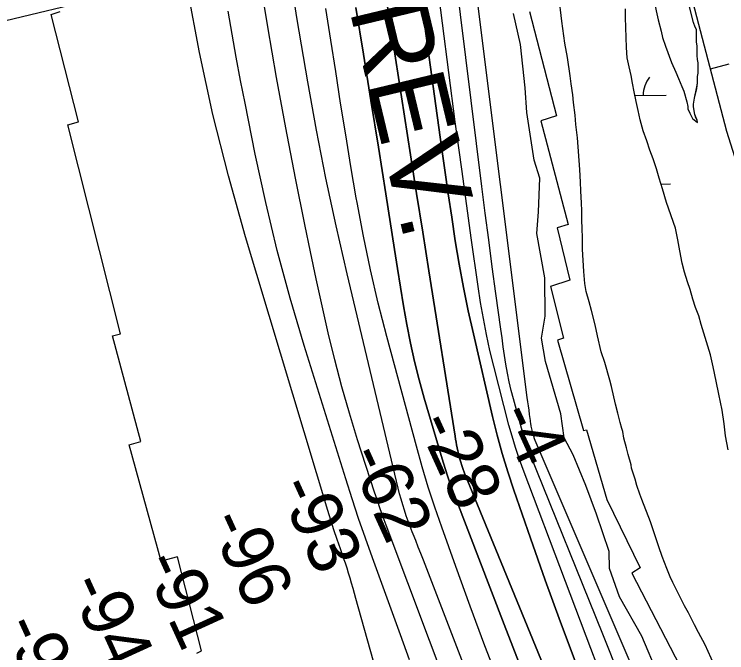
# Model space of a CAD drawing. Extents: x 3567028 to 3605064, y 510945 to 536587.
# Drawn here: x 3578355 to 3579281, y 531241 to 532071 of the extents above; entities that cross this region are included whole.
import ezdxf

# ---------------------------------------------------------------- set-up
doc = ezdxf.new("R2010")
doc.units = 0
for name, color, linetype in [('V-BORW-LINE', 7, 'Continuous'), ('V-RIVR-EDGE', 7, 'Continuous'), ('V-RIVR-RANG', 7, 'Continuous'), ('V-RRAP-RVMT', 7, 'Continuous'), ('V-RRAP-RVMT-IDEN', 7, 'Continuous'), ('V-SITE-VEGE', 7, 'Continuous'), ('V-TOPO-DPTH', 7, 'Continuous'), ('V-TOPO-MAJR', 7, 'Continuous'), ('V-TOPO-MINR', 7, 'Continuous'), ('V-WETL-SWMP', 7, 'Continuous')]:
    doc.layers.add(name, color=color, linetype=linetype)

msp = doc.modelspace()

# ---------------------------------------------------------------- linework, layer by layer
at = {"layer": 'V-BORW-LINE'}
msp.add_line((3579260.25, 531999.86), (3579284.44, 532006.19), dxfattribs=at)
msp.add_lwpolyline([(3579544.69, 531115.58), (3579495.04, 531277.88), (3579451.04, 531433.5), (3579380.8, 531627.25), (3579329.97, 531764.6), (3579281.59, 531918.4), (3579230.4, 532113.84)], dxfattribs=at)
at = {"layer": 'V-RIVR-EDGE'}
msp.add_lwpolyline([(3579192.44, 531212.2), (3579171.12, 531262.49), (3579141.83, 531313.42), (3579129.05, 531350.22), (3579128.5, 531372.28), (3579112.07, 531420.72), (3579098.07, 531458.13), (3579081.63, 531498), (3579070.04, 531520.09), (3579065.83, 531551.35), (3579045.78, 531619.41), (3579040.34, 531649.45), (3579045.31, 531678.23), (3579044.82, 531727.87), (3579034.55, 531785.49), (3579036.45, 531813.67), (3579038.4, 531857.78), (3579031.11, 531881.08), (3579021.46, 531942.99), (3579019.08, 531974.86), (3579013.1, 532031.24), (3579004, 532071.71)], dxfattribs=at)
at = {"layer": 'V-RIVR-RANG'}
msp.add_line((3579599.9, 532363.51), (3578219.06, 532032.29), dxfattribs=at)
at = {"layer": 'V-RRAP-RVMT'}
for p, q in [((3578402.67, 532070.27), (3578414.66, 532074.07)), ((3578438.32, 531930.69), (3578402.67, 532070.27)), ((3579025.11, 532074.05), (3579060, 531938.56)), ((3579060, 531938.56), (3579039.5, 531932.16)), ((3578424.57, 531926.86), (3578438.32, 531930.69)), ((3579039.5, 531932.16), (3579075.14, 531797.42)), ((3578493.13, 531655.46), (3578424.57, 531926.86)), ((3579075.14, 531797.42), (3579061.04, 531793.05)), ((3579061.04, 531793.05), (3579077.29, 531725.1)), ((3579077.29, 531725.1), (3579052.32, 531716.62)), ((3579052.32, 531716.62), (3579069.06, 531649.64)), ((3578482.61, 531652.82), (3578493.13, 531655.46)), ((3578519.46, 531515.29), (3578482.61, 531652.82)), ((3579069.06, 531649.64), (3579061.46, 531647.06)), ((3579061.46, 531647.06), (3579095.27, 531529.8)), ((3579095.27, 531529.8), (3579098.94, 531530.7)), ((3579098.94, 531530.7), (3579125.69, 531440.08)), ((3578504.36, 531510.82), (3578519.46, 531515.29)), ((3578546.05, 531359.92), (3578504.36, 531510.82)), ((3579125.69, 531440.08), (3579168.82, 531351.3)), ((3578567.18, 531365.29), (3578546.05, 531359.92)), ((3578598.3, 531243.32), (3578567.18, 531365.29)), ((3579168.82, 531351.3), (3579158.16, 531344.38)), ((3579158.16, 531344.38), (3579220.44, 531223.82)), ((3578592.1, 531240.14), (3578598.3, 531243.32))]:
    msp.add_line(p, q, dxfattribs=at)
at = {"layer": 'V-SITE-VEGE'}
for points in [[(3579174.4, 532144.03), (3579176.51, 532136.23), (3579182.23, 532109.23), (3579185.24, 532096.33), (3579186.44, 532089.14), (3579192.46, 532063.34), (3579196.07, 532048.65), (3579197.88, 532040.55), (3579201.79, 532029.15)], [(3579131.52, 531587.05), (3579129.42, 531595.15), (3579122.8, 531618.24), (3579118.29, 531632.04), (3579113.17, 531652.73), (3579110.16, 531667.13), (3579105.35, 531685.72), (3579102.64, 531696.82), (3579098.73, 531710.32), (3579096.92, 531720.52), (3579095.41, 531736.11), (3579093.89, 531765.51), (3579093.88, 531777.51), (3579093.57, 531794.91), (3579092.96, 531800.31), (3579092.95, 531815.6), (3579092.65, 531825.2), (3579091.74, 531841.1), (3579091.43, 531852.2), (3579090.51, 531868.7), (3579087.48, 531909.8), (3579085.37, 531927.49), (3579084.16, 531939.49), (3579082.35, 531955.99), (3579081.14, 531965.89), (3579079.03, 531980.28), (3579077.82, 531990.78), (3579074.21, 532014.48), (3579070.9, 532033.07), (3579066.97, 532061.57), (3579063.05, 532095.16)], [(3579201.79, 532029.15), (3579209.6, 532007.86), (3579215.31, 531995.26), (3579218.62, 531987.17), (3579223.12, 531976.67), (3579225.53, 531970.67), (3579229.74, 531956.58), (3579230.95, 531950.58), (3579230.95, 531947.58), (3579233.35, 531941.88), (3579236.96, 531935.28), (3579243.56, 531929.89), (3579242.96, 531932.89), (3579241.46, 531935.89), (3579239.95, 531940.39), (3579239.05, 531944.88), (3579238.14, 531950.58), (3579238.14, 531953.58), (3579239.33, 531961.69), (3579242.33, 531973.98), (3579243.22, 531980.89), (3579243.22, 531983.89), (3579243.51, 531989.89), (3579244.11, 531994.09), (3579244.1, 532007.58), (3579243.5, 532011.78), (3579243.19, 532017.18), (3579242.88, 532029.48), (3579242.28, 532034.28), (3579241.97, 532041.78), (3579241.97, 532050.78), (3579240.17, 532053.78), (3579238.06, 532060.08), (3579232.95, 532080.17)], [(3579264.98, 531225.07), (3579253.56, 531251.16), (3579244.85, 531267.06), (3579239.45, 531277.25), (3579231.64, 531292.54), (3579226.53, 531301.84), (3579211.51, 531332.13), (3579207.9, 531339.62), (3579203.39, 531350.42), (3579200.39, 531357.92), (3579197.38, 531366.01), (3579193.17, 531378.31), (3579190.17, 531387.61), (3579182.35, 531411), (3579170.93, 531439.79), (3579168.52, 531446.99), (3579164.62, 531458.08), (3579162.21, 531466.48), (3579157.7, 531480.88), (3579157.1, 531485.07), (3579153.19, 531498.27), (3579151.08, 531507.27), (3579147.47, 531519.87), (3579146.26, 531528.56), (3579145.06, 531532.16), (3579142.96, 531539.96), (3579139.95, 531552.26), (3579136.94, 531563.95), (3579131.52, 531587.05)]]:
    msp.add_lwpolyline(points, dxfattribs=at)
at = {"layer": 'V-TOPO-DPTH'}
for points in [[(3579165.47, 531151.78), (3579120.36, 531264.91), (3579025.47, 531499.76), (3579022.78, 531506.76), (3579020.25, 531513.81), (3579017.95, 531520.94), (3579015.82, 531528.12), (3579003.97, 531570.69), (3579001.07, 531581.85), (3578998.44, 531593.06), (3578996.21, 531604.36), (3578994.24, 531615.72), (3578992.51, 531627.13), (3578990.81, 531638.54), (3578989.17, 531649.97), (3578987.58, 531661.39), (3578981.22, 531707.87), (3578976.53, 531742.55), (3578971.94, 531777.24), (3578967.47, 531811.95), (3578963.08, 531846.66), (3578900.86, 532346.53)], [(3578879.54, 532121.47), (3578910.52, 531898.44), (3578914.84, 531867.88), (3578919.26, 531837.33), (3578923.81, 531806.81), (3578928.47, 531776.3), (3578933.54, 531745.87), (3578939.06, 531715.52), (3578945.26, 531685.31), (3578951.91, 531655.18), (3578976.91, 531547.79), (3578982.92, 531523.66), (3578989.43, 531499.68), (3578996.69, 531475.92), (3579004.44, 531452.3), (3579026.07, 531389.74), (3579045.35, 531335.08), (3579065.09, 531280.58), (3579085.51, 531226.33)], [(3579085.51, 531226.33), (3579065.09, 531280.58), (3579045.35, 531335.08), (3579026.07, 531389.74), (3579004.44, 531452.3), (3578996.69, 531475.92), (3578989.43, 531499.68), (3578982.92, 531523.66), (3578976.91, 531547.79), (3578951.91, 531655.18), (3578945.26, 531685.31), (3578939.06, 531715.52), (3578933.54, 531745.87), (3578928.47, 531776.3), (3578923.81, 531806.81), (3578919.26, 531837.33), (3578914.84, 531867.88), (3578910.52, 531898.44), (3578879.54, 532121.47)], [(3578838.91, 532088.73), (3578846.63, 532038.46), (3578854.44, 531988.21), (3578862.31, 531937.97), (3578870.24, 531887.74), (3578878.18, 531837.5), (3578886.14, 531787.27), (3578894.11, 531737.05), (3578928.24, 531522.08), (3578928.85, 531518.34), (3578929.47, 531514.61), (3578930.12, 531510.87), (3578930.79, 531507.14), (3578931.54, 531503.43), (3578932.38, 531499.75), (3578933.37, 531496.09), (3578934.44, 531492.47), (3578938.26, 531480.44), (3578938.8, 531478.82), (3578939.97, 531475.6), (3578940.6, 531474), (3579080.39, 531133.25)], [(3579080.39, 531133.25), (3578940.6, 531474), (3578939.97, 531475.6), (3578938.8, 531478.82), (3578938.26, 531480.44), (3578934.44, 531492.47), (3578933.37, 531496.09), (3578932.38, 531499.75), (3578931.54, 531503.43), (3578930.79, 531507.14), (3578930.12, 531510.87), (3578929.47, 531514.61), (3578928.85, 531518.34), (3578928.24, 531522.08), (3578894.11, 531737.05), (3578886.14, 531787.27), (3578878.18, 531837.5), (3578870.24, 531887.74), (3578862.31, 531937.97), (3578854.44, 531988.21), (3578846.63, 532038.46), (3578838.91, 532088.73)], [(3578798.97, 532079.45), (3578808.91, 532018.92), (3578818.73, 531958.37), (3578828.38, 531897.79), (3578837.91, 531837.19), (3578849.2, 531764.7), (3578853.08, 531740.35), (3578857.06, 531716.02), (3578861.21, 531691.71), (3578865.46, 531667.42), (3578870.19, 531643.24), (3578875.45, 531619.18), (3578881.51, 531595.31), (3578888.09, 531571.57), (3578911.36, 531492.8), (3578915.2, 531480.38), (3578919.23, 531468.02), (3578923.56, 531455.77), (3578928.09, 531443.59), (3578992.11, 531277.63), (3579028.9, 531182.55)], [(3579028.9, 531182.55), (3578992.11, 531277.63), (3578928.09, 531443.59), (3578923.56, 531455.77), (3578919.23, 531468.02), (3578915.2, 531480.38), (3578911.36, 531492.8), (3578888.09, 531571.57), (3578881.51, 531595.31), (3578875.45, 531619.18), (3578870.19, 531643.24), (3578865.46, 531667.42), (3578861.21, 531691.71), (3578857.06, 531716.02), (3578853.08, 531740.35), (3578849.2, 531764.7), (3578837.91, 531837.19), (3578828.38, 531897.79), (3578818.73, 531958.37), (3578808.91, 532018.92), (3578798.97, 532079.45)]]:
    msp.add_lwpolyline(points, dxfattribs=at)
at = {"layer": 'V-TOPO-MAJR'}
msp.add_lwpolyline([(3578986.64, 531198.79), (3578967.04, 531249.93), (3578947.95, 531301.26), (3578929.19, 531352.72), (3578910.81, 531403.88), (3578901.81, 531429.95), (3578893.23, 531456.15), (3578885.3, 531482.56), (3578877.8, 531509.1), (3578839.3, 531651.93), (3578828.29, 531695.12), (3578818.07, 531738.49), (3578809.02, 531782.12), (3578800.77, 531825.92), (3578799.73, 531831.86), (3578792.72, 531872.85), (3578785.89, 531913.86), (3578779.32, 531954.91), (3578772.93, 531996), (3578766.58, 532037.09), (3578760.08, 532078.15)], dxfattribs=at)
at = {"layer": 'V-TOPO-MINR'}
for points in [[(3579226.28, 531064.84), (3579032.35, 531516.86), (3579031.52, 531518.95), (3579031.16, 531520.02), (3579030.82, 531521.09), (3579028.76, 531528.12), (3579028.27, 531529.93), (3579027.45, 531533.59), (3579027.13, 531535.44), (3579026.57, 531539.15), (3579026.31, 531541.01), (3579026.05, 531542.86), (3579025.03, 531550.34), (3579024.28, 531555.93), (3579023.54, 531561.53), (3579022.81, 531567.13), (3579022.1, 531572.73), (3578917.64, 532406.89)], [(3579165.47, 531151.78), (3579120.36, 531264.91), (3579025.47, 531499.76), (3579022.78, 531506.76), (3579020.25, 531513.81), (3579017.95, 531520.94), (3579015.82, 531528.12), (3579003.97, 531570.69), (3579001.07, 531581.85), (3578998.44, 531593.06), (3578996.21, 531604.36), (3578994.24, 531615.72), (3578992.51, 531627.13), (3578990.81, 531638.54), (3578989.17, 531649.97), (3578987.58, 531661.39), (3578981.22, 531707.87), (3578976.53, 531742.55), (3578971.94, 531777.24), (3578967.47, 531811.95), (3578963.08, 531846.66), (3578900.86, 532346.53)], [(3579137.85, 531159.64), (3579104.83, 531246.55), (3579071.83, 531333.48), (3579016.64, 531478.98), (3579011.5, 531493.24), (3579006.67, 531507.59), (3579002.31, 531522.1), (3578998.27, 531536.71), (3578978.49, 531613.06), (3578973.48, 531633.65), (3578968.89, 531654.33), (3578964.91, 531675.13), (3578961.35, 531696.02), (3578958.16, 531716.98), (3578955.04, 531737.95), (3578952.02, 531758.93), (3578949.07, 531779.93), (3578937.17, 531866.38), (3578928.45, 531930.63), (3578919.92, 531994.9), (3578911.64, 532059.2), (3578903.55, 532123.53)], [(3578923.07, 531181.66), (3578838.57, 531406.51), (3578834.62, 531417.23), (3578830.78, 531427.98), (3578827.08, 531438.78), (3578823.48, 531449.62), (3578801.44, 531517.58), (3578790.77, 531551.99), (3578780.73, 531586.57), (3578771.6, 531621.4), (3578763.08, 531656.4), (3578755.16, 531691.56), (3578747.44, 531726.76), (3578740, 531762.02), (3578732.74, 531797.32), (3578720.65, 531857.4), (3578707.94, 531922.85), (3578695.83, 531988.41), (3578684.62, 532054.13), (3578674.01, 532119.95)], [(3579085.51, 531226.33), (3579065.09, 531280.58), (3579045.35, 531335.08), (3579026.07, 531389.74), (3579004.44, 531452.3), (3578996.69, 531475.92), (3578989.43, 531499.68), (3578982.92, 531523.66), (3578976.91, 531547.79), (3578951.91, 531655.18), (3578945.26, 531685.31), (3578939.06, 531715.52), (3578933.54, 531745.87), (3578928.47, 531776.3), (3578923.81, 531806.81), (3578919.26, 531837.33), (3578914.84, 531867.88), (3578910.52, 531898.44), (3578879.54, 532121.47)], [(3578841.09, 531161.67), (3578799.2, 531311.24), (3578797.33, 531317.87), (3578795.46, 531324.49), (3578793.56, 531331.11), (3578791.66, 531337.72), (3578789.69, 531344.31), (3578787.64, 531350.88), (3578785.48, 531357.41), (3578783.23, 531363.91), (3578779.03, 531375.75), (3578774.71, 531388.19), (3578770.52, 531400.67), (3578766.51, 531413.2), (3578762.63, 531425.78), (3578655.59, 531781.28), (3578633.32, 531860.59), (3578613.05, 531940.37), (3578595.78, 532020.86), (3578580.51, 532101.81)], [(3579080.39, 531133.25), (3578940.6, 531474), (3578939.97, 531475.6), (3578938.8, 531478.82), (3578938.26, 531480.44), (3578934.44, 531492.47), (3578933.37, 531496.09), (3578932.38, 531499.75), (3578931.54, 531503.43), (3578930.79, 531507.14), (3578930.12, 531510.87), (3578929.47, 531514.61), (3578928.85, 531518.34), (3578928.24, 531522.08), (3578894.11, 531737.05), (3578886.14, 531787.27), (3578878.18, 531837.5), (3578870.24, 531887.74), (3578862.31, 531937.97), (3578854.44, 531988.21), (3578846.63, 532038.46), (3578838.91, 532088.73)], [(3578978.29, 531124.51), (3578886.88, 531361.27), (3578883.6, 531369.72), (3578880.3, 531378.16), (3578876.98, 531386.59), (3578873.64, 531395.01), (3578872.45, 531398), (3578869.75, 531404.95), (3578867.15, 531411.93), (3578864.67, 531418.96), (3578862.29, 531426.01), (3578860.06, 531433.12), (3578857.94, 531440.26), (3578856.01, 531447.45), (3578854.19, 531454.68), (3578787.63, 531733.42), (3578773.46, 531795.45), (3578760.11, 531857.66), (3578747.99, 531920.11), (3578736.68, 531982.73), (3578722.87, 532063.82), (3578719.16, 532086.03)], [(3579028.9, 531182.55), (3578992.11, 531277.63), (3578928.09, 531443.59), (3578923.56, 531455.77), (3578919.23, 531468.02), (3578915.2, 531480.38), (3578911.36, 531492.8), (3578888.09, 531571.57), (3578881.51, 531595.31), (3578875.45, 531619.18), (3578870.19, 531643.24), (3578865.46, 531667.42), (3578861.21, 531691.71), (3578857.06, 531716.02), (3578853.08, 531740.35), (3578849.2, 531764.7), (3578837.91, 531837.19), (3578828.38, 531897.79), (3578818.73, 531958.37), (3578808.91, 532018.92), (3578798.97, 532079.45)], [(3578868.66, 531231.47), (3578857.03, 531264.04), (3578820.56, 531364.09), (3578811.47, 531389.59), (3578802.62, 531415.17), (3578794.13, 531440.88), (3578785.89, 531466.67), (3578731.85, 531640.03), (3578713.71, 531701.59), (3578696.87, 531763.49), (3578681.97, 531825.88), (3578668.37, 531888.6), (3578655.08, 531954.87), (3578649.24, 531984.73), (3578643.59, 532014.64), (3578638.23, 532044.59), (3578633.06, 532074.58)]]:
    msp.add_lwpolyline(points, dxfattribs=at)
at = {"layer": 'V-WETL-SWMP'}
for p, q in [((3579186.44, 532089.13), (3579192.46, 532063.34)), ((3579149.85, 532066.32), (3579149.84, 532077.45)), ((3579238.05, 532060.08), (3579232.94, 532080.17)), ((3579151.06, 532027.53), (3579149.85, 532066.32)), ((3579192.46, 532063.34), (3579196.07, 532048.64)), ((3579240.16, 532053.78), (3579238.05, 532060.08)), ((3579241.96, 532050.78), (3579240.16, 532053.78)), ((3579241.97, 532041.78), (3579241.96, 532050.78)), ((3579196.07, 532048.64), (3579197.87, 532040.55)), ((3579197.87, 532040.55), (3579201.78, 532029.15)), ((3579242.27, 532034.28), (3579241.97, 532041.78)), ((3579242.88, 532029.48), (3579242.27, 532034.28)), ((3579151.85, 532013.9), (3579151.06, 532027.53)), ((3579201.78, 532029.15), (3579209.6, 532007.86)), ((3579243.19, 532017.18), (3579242.88, 532029.48)), ((3579154.48, 532002.37), (3579151.85, 532013.9)), ((3579243.49, 532011.78), (3579243.19, 532017.18)), ((3579209.6, 532007.86), (3579215.3, 531995.26)), ((3579244.09, 532007.58), (3579243.49, 532011.78)), ((3579244.1, 531994.08), (3579244.09, 532007.58)), ((3579156.98, 531990.84), (3579154.48, 532002.37)), ((3579215.3, 531995.26), (3579218.61, 531987.17)), ((3579243.51, 531989.88), (3579244.1, 531994.08)), ((3579158.95, 531980.88), (3579156.98, 531990.84)), ((3579218.61, 531987.17), (3579223.12, 531976.67)), ((3579243.21, 531983.88), (3579243.51, 531989.88)), ((3579161.19, 531969.88), (3579158.95, 531980.88)), ((3579223.12, 531976.67), (3579225.52, 531970.67)), ((3579242.32, 531973.98), (3579243.21, 531980.88)), ((3579243.21, 531980.88), (3579243.21, 531983.88)), ((3579163.69, 531957.04), (3579161.19, 531969.88)), ((3579225.52, 531970.67), (3579229.73, 531956.58)), ((3579239.33, 531961.68), (3579242.32, 531973.98)), ((3579162.13, 531965.06), (3579202.82, 531965.41)), ((3579166.19, 531945.38), (3579163.69, 531957.04)), ((3579238.13, 531953.58), (3579239.33, 531961.68)), ((3579229.73, 531956.58), (3579230.94, 531950.58)), ((3579230.94, 531950.58), (3579230.94, 531947.58)), ((3579230.94, 531947.58), (3579233.34, 531941.88)), ((3579238.14, 531950.58), (3579238.13, 531953.58)), ((3579239.04, 531944.88), (3579238.14, 531950.58)), ((3579168.95, 531933.59), (3579166.19, 531945.38)), ((3579233.34, 531941.88), (3579236.95, 531935.28)), ((3579239.94, 531940.39), (3579239.04, 531944.88)), ((3579241.45, 531935.89), (3579239.94, 531940.39)), ((3579172.63, 531919.18), (3579168.95, 531933.59)), ((3579236.95, 531935.28), (3579243.55, 531929.89)), ((3579242.95, 531932.89), (3579241.45, 531935.89)), ((3579243.55, 531929.89), (3579242.95, 531932.89)), ((3579177.62, 531905.94), (3579172.63, 531919.18)), ((3579181.3, 531894.15), (3579177.62, 531905.94)), ((3579185.89, 531882.63), (3579181.3, 531894.15)), ((3579189.96, 531869.52), (3579185.89, 531882.63)), ((3579193.38, 531857.47), (3579189.96, 531869.52)), ((3579197.98, 531843.58), (3579193.38, 531857.47)), ((3579195.88, 531849.91), (3579208.39, 531850.02)), ((3579203.1, 531825.9), (3579197.98, 531843.58)), ((3579214.66, 531792.62), (3579203.1, 531825.9)), ((3579217.68, 531777.56), (3579214.66, 531792.62)), ((3579220.45, 531763.01), (3579217.68, 531777.56)), ((3579223.6, 531747.03), (3579220.45, 531763.01)), ((3579226.63, 531735.37), (3579223.6, 531747.03)), ((3579230.57, 531722.92), (3579226.63, 531735.37)), ((3579233.98, 531712.84), (3579230.57, 531722.92)), ((3579237.14, 531700.26), (3579233.98, 531712.84)), ((3579240.68, 531689.52), (3579237.14, 531700.26)), ((3579245.02, 531678.51), (3579240.68, 531689.52)), ((3579248.17, 531667.51), (3579245.02, 531678.51)), ((3579260.13, 531627.94), (3579248.17, 531667.51)), ((3579263.68, 531612.35), (3579260.13, 531627.94)), ((3579267.62, 531593.75), (3579263.68, 531612.35)), ((3579271.3, 531576.71), (3579267.62, 531593.75)), ((3579275.51, 531556.01), (3579271.3, 531576.71)), ((3579278.02, 531538.32), (3579275.51, 531556.01)), ((3579279.86, 531522.6), (3579278.02, 531538.32)), ((3579283.15, 531504.52), (3579279.86, 531522.6))]:
    msp.add_line(p, q, dxfattribs=at)
msp.add_arc((3579208.06, 531965.93), 35.25, 139.71154, 181.2552, dxfattribs=at)

# ---------------------------------------------------------------- texts
at = {"layer": 'V-RIVR-RANG'}
for s, p in [('-4', (3578982.67, 531550.6)), ('-28', (3578877.9, 531539.33)), ('-62', (3578787.25, 531497.09)), ('-93', (3578695.95, 531456.3)), ('-96', (3578606.17, 531412.15)), ('-91', (3578520.89, 531358.16)), ('-94', (3578424.11, 531329.37)), ('-91', (3578338.72, 531275.62))]:
    msp.add_text(s, height=67, rotation=294.51719, dxfattribs=at).set_placement(p)
at = {"layer": 'V-RRAP-RVMT-IDEN'}
msp.add_text('REV.', height=100, rotation=283.47965, dxfattribs=at).set_placement((3578790.45, 532076.92))

doc.saveas('drawing.dxf')
